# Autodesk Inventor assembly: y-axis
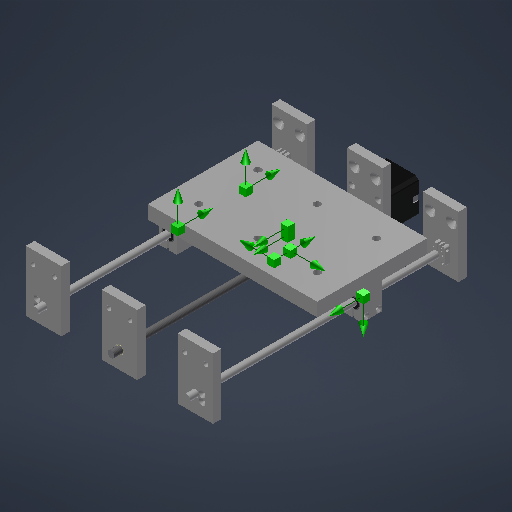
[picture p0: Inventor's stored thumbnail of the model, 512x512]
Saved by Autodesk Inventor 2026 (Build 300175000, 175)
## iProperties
Created: 2025-04
Part Number: y-axis
Material: Generisch
Document SubType Name: Assembly
Designer: BennF
Author: BennF
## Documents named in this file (15)
- C:\Users\BennF\Nextcloud\Benedikt\FabAcademy\week12\CAD\y-axis\y-axis.iam
- C:\Users\BennF\Nextcloud\Benedikt\FabAcademy\week12\CAD\y-axis\y_axis_mounting_plate.ipt
- C:\Users\BennF\Nextcloud\Benedikt\FabAcademy\week12\CAD\y-axis\y_axis_mounting_plate_stepper.ipt
- C:\Users\BennF\Nextcloud\Benedikt\FabAcademy\week12\CAD\y-axis\stepper_Motor.ipt
- C:\Users\BennF\Nextcloud\Benedikt\FabAcademy\week12\CAD\bushig_8mm.ipt
- C:\Users\BennF\Nextcloud\Benedikt\FabAcademy\week12\CAD\y-axis\y_axis_guide_rod_mounting_plate_1.ipt
- C:\Users\BennF\Nextcloud\Benedikt\FabAcademy\week12\CAD\y-axis\y_axis_guide_rod_mounting_plate_2.ipt
- C:\Users\BennF\Nextcloud\Benedikt\FabAcademy\week12\CAD\y-axis\y_axis_8mm_rod.ipt
- C:\Users\BennF\Nextcloud\Benedikt\FabAcademy\week12\CAD\y-axis\y_axis_side_slate.ipt
- C:\Users\BennF\Nextcloud\Benedikt\FabAcademy\week12\CAD\LM8UU.ipt
- C:\Users\BennF\Nextcloud\Benedikt\FabAcademy\week12\CAD\y-axis\machine_bed.ipt
- C:\Users\BennF\Nextcloud\Benedikt\FabAcademy\week12\CAD\y-axis\y_axis_8mm_rod_mount.ipt
- C:\Users\BennF\Nextcloud\Benedikt\FabAcademy\week12\CAD\y-axis\y_axis_slate.ipt
- C:\Users\BennF\Nextcloud\Benedikt\FabAcademy\week12\CAD\t8_screw_nut.ipt
- C:\Users\BennF\Nextcloud\Benedikt\FabAcademy\week12\CAD\y-axis\waste_board.ipt
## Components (25 placed, 14 different names)
1. stepper_Motor:1 — Insert:1, Insert:2, Insert:4
2. y_axis_mounting_plate_stepper:1
3. y_axis_mounting_plate:1 — Insert:3, Angle:1, Flush:1, Flush:2, Flush:5, Flush:6
4. bushig_8mm:1 — Insert:3, Insert:4
5. y_axis_guide_rod_mounting_plate_1:1 — Flush:1, Flush:8, Mate:2, Flush:10, Insert:14, Insert:18
6. y_axis_guide_rod_mounting_plate_2:1 — Flush:3, Flush:5, Flush:10, Insert:5, Insert:13, Insert:17
7. y_axis_guide_rod_mounting_plate_1:2 — Flush:4, Flush:6, Flush:9, Insert:6, Insert:15, Insert:19
8. y_axis_guide_rod_mounting_plate_2:2 — Flush:2, Flush:7, Mate:1, Flush:9, Insert:16, Insert:20
9. y_axis_8mm_rod:1 — Insert:6, Cylindrical:1
10. y_axis_8mm_rod:2 — Insert:5
11. y_axis_side_slate:1 — Insert:9, Insert:12, Flush:11
12. y_axis_side_slate:2 — Insert:8, Insert:11
13. y_axis_side_slate:3 — Insert:7, Insert:10
14. LM8UU:1 — Insert:7
15. LM8UU:2 — Insert:8
16. LM8UU:3 — Insert:9, Cylindrical:1
17. machine_bed:1
18. y_axis_8mm_rod_mount:1 — Insert:13, Insert:17
19. y_axis_8mm_rod_mount:2 — Insert:14, Insert:18
20. y_axis_8mm_rod_mount:3 — Insert:15, Insert:19
21. y_axis_8mm_rod_mount:4 — Insert:16, Insert:20
22. y_axis_slate:1 — Insert:21, Insert:22, Insert:23
23. t8_screw_nut:1 — Insert:22
24. t8_screw_nut:2 — Insert:21
25. waste_board:1 — Insert:28, Insert:29
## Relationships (40: Insert 25, Flush 11, Mate 2, Angle 1, CylindricalJoint 1)
- Insert:1: stepper_Motor:1
- Insert:2: stepper_Motor:1
- Insert:3: y_axis_mounting_plate:1 ↔ bushig_8mm:1
- Insert:4: stepper_Motor:1 ↔ bushig_8mm:1
- Angle:1: y_axis_mounting_plate:1
- Flush:1: y_axis_mounting_plate:1 ↔ y_axis_guide_rod_mounting_plate_1:1
- Flush:2: y_axis_mounting_plate:1 ↔ y_axis_guide_rod_mounting_plate_2:2
- Flush:3: y_axis_guide_rod_mounting_plate_2:1
- Flush:4: y_axis_guide_rod_mounting_plate_1:2
- Flush:5: y_axis_mounting_plate:1 ↔ y_axis_guide_rod_mounting_plate_2:1
- Flush:6: y_axis_mounting_plate:1 ↔ y_axis_guide_rod_mounting_plate_1:2
- Flush:7: y_axis_guide_rod_mounting_plate_2:2
- Flush:8: y_axis_guide_rod_mounting_plate_1:1
- Mate:1: y_axis_guide_rod_mounting_plate_2:2
- Mate:2: y_axis_guide_rod_mounting_plate_1:1
- Flush:9: y_axis_guide_rod_mounting_plate_1:2 ↔ y_axis_guide_rod_mounting_plate_2:2
- Flush:10: y_axis_guide_rod_mounting_plate_1:1 ↔ y_axis_guide_rod_mounting_plate_2:1
- Insert:5: y_axis_guide_rod_mounting_plate_2:1 ↔ y_axis_8mm_rod:2
- Insert:6: y_axis_guide_rod_mounting_plate_1:2 ↔ y_axis_8mm_rod:1
- Insert:7: y_axis_side_slate:3 ↔ LM8UU:1
- Insert:8: y_axis_side_slate:2 ↔ LM8UU:2
- Insert:9: y_axis_side_slate:1 ↔ LM8UU:3
- Insert:10: y_axis_side_slate:3
- Insert:11: y_axis_side_slate:2
- Insert:12: y_axis_side_slate:1
- Insert:13: y_axis_guide_rod_mounting_plate_2:1 ↔ y_axis_8mm_rod_mount:1
- Insert:14: y_axis_guide_rod_mounting_plate_1:1 ↔ y_axis_8mm_rod_mount:2
- Insert:15: y_axis_guide_rod_mounting_plate_1:2 ↔ y_axis_8mm_rod_mount:3
- Insert:16: y_axis_guide_rod_mounting_plate_2:2 ↔ y_axis_8mm_rod_mount:4
- Insert:17: y_axis_guide_rod_mounting_plate_2:1 ↔ y_axis_8mm_rod_mount:1
- Insert:18: y_axis_guide_rod_mounting_plate_1:1 ↔ y_axis_8mm_rod_mount:2
- Insert:19: y_axis_guide_rod_mounting_plate_1:2 ↔ y_axis_8mm_rod_mount:3
- Insert:20: y_axis_guide_rod_mounting_plate_2:2 ↔ y_axis_8mm_rod_mount:4
- Flush:11: y_axis_side_slate:1
- Cylindrical:1: y_axis_8mm_rod:1 ↔ LM8UU:3
- Insert:21: y_axis_slate:1 ↔ t8_screw_nut:2
- Insert:22: y_axis_slate:1 ↔ t8_screw_nut:1
- Insert:23: y_axis_slate:1
- Insert:28: waste_board:1
- Insert:29: waste_board:1
